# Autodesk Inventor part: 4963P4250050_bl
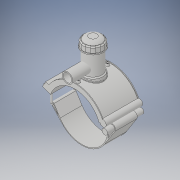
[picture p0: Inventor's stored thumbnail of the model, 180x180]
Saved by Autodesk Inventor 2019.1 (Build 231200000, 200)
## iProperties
Created: 2017-07
Part Number: 4963P4250050_bl
Material: Generic
Document SubType Name: Modeling
Designer: KIM
Density: 1 g/cm^3
Appearance: Default
Author: KIM
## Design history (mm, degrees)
derived "4963P4.ipt"
feature "Solid1::4963P4.ipt" dims "ScaleForDerivedMember" = 10
feature "Solid2::4963P4.ipt" dims "ScaleForDerivedMember" = 10
feature "Solid3::4963P4.ipt" dims "ScaleForDerivedMember" = 10
tag "TaggingFeature1"
body "Solid1"
body "Solid2"
body "Solid3"
other parameters: "B_" = 252 [user parameter], "L_" = 176 [user parameter], "d_t" = 6 [user parameter], "H_2" = 177 [user parameter], "H_1" = 64 [user parameter], "H_" = 123 [user parameter], "d148" = 3.75 [user parameter], "d160" = 3.75 [user parameter], "d169" = 3.75 [user parameter], "d192" = 8 [user parameter], "d2" = 327.6 [user parameter], "d3" = 62.5 [user parameter], "d4" = 176 [user parameter], "d5" = 0 [user parameter], "d6" = 0.1 [user parameter], "d8" = 0 [user parameter], "d19" = 6 [user parameter], "d20" = 6 [user parameter], "d21" = 105.6 [user parameter], "d23" = 0 [user parameter], "d24" = 52.8 [user parameter], "d26" = 0 [user parameter], "d27" = 3 [user parameter], "d28" = 3 [user parameter], "d29" = 3 [user parameter], "d30" = 83.33333 [user parameter], "d31" = 6 [user parameter], "d32" = 0 [user parameter], "d33" = 0 [user parameter], "d34" = 0.6 [user parameter], "d40" = 150.8 [user parameter], "d43" = 0 [user parameter], "d45" = 0 [user parameter], "d47" = 250.6 [user parameter], "d70" = 15 [user parameter], "d72" = 0 [user parameter], "d73" = 6 [user parameter], "d75" = 5 [user parameter], "d76" = 0 [user parameter], "d77" = 12.5 [user parameter], "d78" = 155 [user parameter], "d79" = 15 [user parameter], "d80" = 70.4 [user parameter], "d82" = 5 deg [user parameter], "d84" = 4 [user parameter], "d85" = 14 [user parameter], "d86" = 0 [user parameter], "d87" = 3 [user parameter], "d88" = 0 [user parameter], "d89" = 1 [user parameter], "d90" = 1 [user parameter], "d91" = 140.8 [user parameter], "d92" = 0 [user parameter], "d93" = 0.5 [user parameter], "d94" = 131.57895 [user parameter], "d96" = 295.8 [user parameter], "d97" = 3.52 [user parameter], "d98" = 0 [user parameter], "d102" = 2.5 [user parameter], "d120" = 140 deg [user parameter], "d121" = 24.228 [user parameter], "d122" = 20 deg [user parameter], "d124" = 174 [user parameter], "d126" = 0 [user parameter], "d143" = 257.5 [user parameter], "d145" = 30.76923 [user parameter], "d149" = 3.75 [user parameter], "d150" = 33.84615 [user parameter], "d153" = 176 [user parameter], "d154" = 0 [user parameter], "d156" = 145 [user parameter], "d157" = 160 deg [user parameter], "d159" = 8 [user parameter], "d161" = 3.75 [user parameter], "d162" = 105.6 [user parameter], "d163" = 0 [user parameter], "d164" = 125 [user parameter], "d167" = 25 [user parameter], "d168" = 141.46341 [user parameter], "d170" = 3.75 [user parameter], "d172" = 0 [user parameter], "d173" = 1 [user parameter], "d175" = 125 [user parameter], "d176" = 20 deg [user parameter], "d177" = 17.5 [user parameter], "d180" = 0 [user parameter], "d183" = 16 [user parameter], "d184" = 14 [user parameter], "d185" = 57.2 [user parameter], "d186" = 57.2 [user parameter], "d187" = 145 [user parameter], "d188" = 12 [user parameter], "d189" = 17.5 [user parameter], "d190" = 0 [user parameter], "d191" = 217.5 [user parameter], "d193" = 8 [user parameter], "d194" = 6.16 [user parameter], "d195" = 90 deg [user parameter], "d197" = 0 [user parameter], "d199" = 0 [user parameter], "d202" = 0 [user parameter], "d203" = 177 [user parameter], "d204" = 95 [user parameter], "d206" = 85 [user parameter], "d207" = 132.75 [user parameter], "d208" = 138.06 [user parameter], "d209" = 164.61 [user parameter], "d210" = 86 [user parameter], "d213" = 35.1 [user parameter], "d216" = 0 [user parameter], "d217" = 25 [user parameter], "d218" = 25 [user parameter], "d219" = 5 [user parameter], "d224" = 0 [user parameter], "d225" = 64 [user parameter], "d228" = 123 [user parameter], "d230" = 5 [user parameter]
